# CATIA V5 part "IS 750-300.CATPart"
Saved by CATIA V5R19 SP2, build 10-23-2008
Part number: IS 750-300
Bounding box of the stored display mesh (mm): x -24.865 to 24.865, y -24.997 to 24.997, z 0 to 695
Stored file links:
  C:\Users\Bora\Desktop\3D Katı model\IS serisi\IS 750\IS 750-300.CATPart
  C:\Program Files\Dassault Systemes\B19\intel_a\reffiles\standard\MetricThickPitch.txt
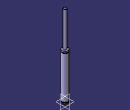
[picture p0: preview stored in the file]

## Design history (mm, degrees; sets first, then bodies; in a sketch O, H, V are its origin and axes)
Body1 (main body)
  Sketch1 on yz-plane, origin (0, 0, 0), H (0, 1, 0), V (0, 0, 1)
    point P1 (25, 379.5)
    point P4 (25, 375.5)
    point P7 (12.5, 694)
    point P9 (12.5, 694)
    point P13 (25, 379.5)
    point P14 (25, 375.5)
    line L1 (25, 379.5) -> (25, 392)
    line L2 (25, 13) -> (25, 375.5)
    line L3 (21.5, 13) -> (21.5, 8)
    arc A1 centre (11.5, 694) radius 1 from (12.5, 694) to (11.5, 695) ccw
    line L4 (12.5, 694) -> (12.5, 392)
    line L5 (25, 0) -> (25, 8)
    arc A2 centre (25, 377.5) radius 2 from (25, 379.5) to (25, 375.5) ccw
    line L6 (11.5, 695) -> (0, 695)
    point P15 (0, 695)
    line L7 (12.5, 392) -> (25, 392)
    line L8 (0, 0) -> (25, 0)
    line L9 (21.5, 13) -> (25, 13)
    line L10 (21.5, 8) -> (25, 8)
    coincidence: P15 V, P1 P13, P4 P14, P7 P9
    tangency: L6 A1
    horizontal: L7 H, L8 H, L9 H, L10 H
  Shaft1: profile Sketch1, axis Sketch1.V, angle 360
  Sketch2 on face of Shaft1 from Sketch1.L8, origin (0, 0, 0), H (1, 0, 0), V (0, -1, 0)
    point P1 (10, 0)
    distance V P1 = 10
  Hole1: placed by Sketch2, at (10, 0, 0) direction (0, 0, 1), diameter 6.647, depth 13, threaded "M8", thread diameter 8, thread depth 13, pitch 1.25
  Sketch3 on face of Shaft1 from Sketch1.L8, origin (0, 0, 0), H (1, 0, 0), V (0, -1, 0)
    point P1 (-10, 0)
    distance P1 V = 10
  Hole2: placed by Sketch3, at (-10, 0, 0) direction (0, 0, 1), diameter 6.647, depth 13, threaded "M8", thread diameter 8, thread depth 13, pitch 1.25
